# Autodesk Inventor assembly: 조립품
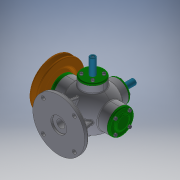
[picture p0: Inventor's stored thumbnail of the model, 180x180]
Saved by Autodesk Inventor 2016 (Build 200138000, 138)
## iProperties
Created: 2019-11
Part Number: 조립품
Material: 일반
Document SubType Name: Assembly
Designer: user
Author: user
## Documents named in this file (17)
- C:\Users\user\Desktop\391120V1004\조립품.iam
- C:\Users\user\Desktop\391120V1004\V-벨트풀리.ipt
- C:\Users\user\Desktop\391120V1004\너트 M8x1.ipt
- C:\Users\user\Desktop\391120V1004\뒤커버.ipt
- C:\Users\user\Desktop\391120V1004\베어링 6202.ipt
- C:\Users\user\Desktop\391120V1004\본체.ipt
- C:\Users\user\Desktop\391120V1004\본체커버.ipt
- C:\Users\user\Desktop\391120V1004\볼트 M4.ipt
- C:\Users\user\Desktop\391120V1004\스프링1.ipt
- C:\Users\user\Desktop\391120V1004\스프링2.ipt
- C:\Users\user\Desktop\391120V1004\슬라이드 커버.ipt
- C:\Users\user\Desktop\391120V1004\슬라이드.ipt
- C:\Users\user\Desktop\391120V1004\앞커버.ipt
- C:\Users\user\Desktop\391120V1004\오일 실.ipt
- C:\Users\user\Desktop\391120V1004\와셔 8x17.ipt
- C:\Users\user\Desktop\391120V1004\축.ipt
- C:\Users\user\Desktop\391120V1004\키 4x4.ipt
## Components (1 placed, 1 different names)
1. V-벨트풀리:1
